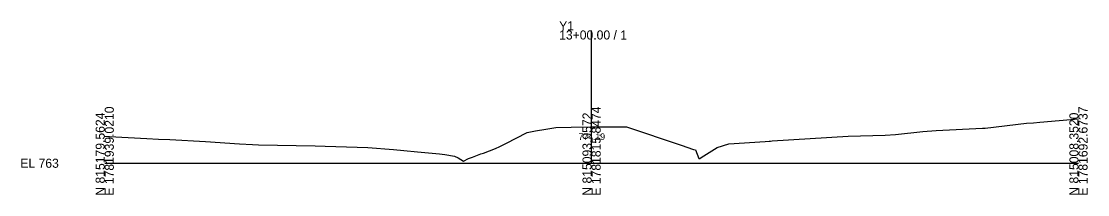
# Model space of a CAD drawing. Extents: x -26 to 3603, y -10 to 9847.
# Drawn here: x -25.7 to 302.8, y 2990.3 to 3043.7 of the extents above; entities that cross this region are included whole.
import ezdxf

# ---------------------------------------------------------------- set-up
doc = ezdxf.new("R2010")
doc.units = 0
for name, color, linetype in [('Exist Cross Section Cell', 7, 'Continuous'), ('Exist XS Center Line Elevation Label', 7, 'Continuous'), ('Exist XS Ground Line', 7, 'Continuous')]:
    doc.layers.add(name, color=color, linetype=linetype)

msp = doc.modelspace()

# ---------------------------------------------------------------- linework, layer by layer
at = {"layer": 'Exist Cross Section Cell'}
for p, q in [((150, 3000), (150, 3040.93)), ((0, 3000), (150, 3000)), ((150, 3000), (300, 3000))]:
    msp.add_line(p, q, dxfattribs=at)
at = {"layer": 'Exist XS Ground Line'}
for p, q in [((286.14, 3012.49), (288.1, 3012.65)), ((288.1, 3012.65), (300, 3013.64)), ((123.54, 3006.08), (130.13, 3009.51)), ((130.13, 3009.51), (132.75, 3009.96)), ((132.75, 3009.96), (135.87, 3010.5)), ((135.87, 3010.5), (139.03, 3011.03)), ((139.03, 3011.03), (143.7, 3011.11)), ((143.7, 3011.11), (149.68, 3011.19)), ((149.68, 3011.19), (150, 3011.19)), ((150, 3011.19), (156.1, 3011.21)), ((156.1, 3011.21), (160.76, 3011.2)), ((160.76, 3011.2), (177.59, 3005.58)), ((243.64, 3008.89), (252.03, 3009.81)), ((252.03, 3009.81), (256.15, 3010.09)), ((256.15, 3010.09), (270.47, 3010.78)), ((270.47, 3010.78), (271.24, 3010.84)), ((271.24, 3010.84), (284.01, 3012.33)), ((284.01, 3012.33), (286.14, 3012.49)), ((0, 3008.32), (1.43, 3008.23)), ((1.43, 3008.23), (13, 3007.61)), ((13, 3007.61), (16.61, 3007.46)), ((16.61, 3007.46), (20.05, 3007.3)), ((20.05, 3007.3), (31, 3006.65)), ((31, 3006.65), (41.51, 3006.02)), ((121.68, 3005.15), (123.54, 3006.08)), ((192.24, 3005.94), (203.44, 3006.71)), ((203.44, 3006.71), (204.72, 3006.81)), ((204.72, 3006.81), (205.13, 3006.82)), ((205.13, 3006.82), (205.66, 3006.86)), ((205.66, 3006.86), (229.08, 3008.35)), ((229.08, 3008.35), (240.42, 3008.65)), ((240.42, 3008.65), (243.64, 3008.89)), ((41.51, 3006.02), (45.51, 3005.79)), ((45.51, 3005.79), (47.36, 3005.71)), ((47.36, 3005.71), (64.81, 3005.31)), ((64.81, 3005.31), (67.88, 3005.21)), ((67.88, 3005.21), (77.8, 3004.99)), ((77.8, 3004.99), (81.03, 3004.81)), ((81.03, 3004.81), (88.95, 3004.19)), ((88.95, 3004.19), (92.14, 3003.91)), ((92.14, 3003.91), (96.4, 3003.53)), ((96.4, 3003.53), (103.19, 3002.87)), ((103.19, 3002.87), (104.81, 3002.68)), ((113.36, 3001.88), (115.88, 3002.94)), ((115.88, 3002.94), (116.73, 3003.15)), ((116.73, 3003.15), (120.35, 3004.54)), ((120.35, 3004.54), (121.68, 3005.15)), ((177.59, 3005.58), (181.41, 3004.21)), ((181.41, 3004.21), (181.98, 3004.11)), ((181.98, 3004.11), (183.04, 3001.41)), ((183.79, 3001.74), (188.7, 3004.81)), ((188.7, 3004.81), (192.24, 3005.94)), ((104.81, 3002.68), (107.74, 3002.21)), ((107.74, 3002.21), (108.86, 3001.62)), ((108.86, 3001.62), (110.55, 3000.67)), ((110.55, 3000.67), (112.08, 3001.46)), ((112.08, 3001.46), (113.36, 3001.88)), ((183.04, 3001.41), (183.36, 3001.44)), ((183.36, 3001.44), (183.79, 3001.74))]:
    msp.add_line(p, q, dxfattribs=at)

# ---------------------------------------------------------------- texts
at = {"layer": 'Exist Cross Section Cell'}
for s, p in [('Y1', (140, 3040.93)), ('13+00.00 / 1', (140, 3038.13)), ('EL 763', (-26, 2998.6))]:
    msp.add_text(s, height=2.8, dxfattribs=at).set_placement(p)
for s, p in [('E 1781939.0210', (2.8, 2990)), ('E 1781815.8474', (152.8, 2990)), ('E 1781692.6737', (302.8, 2990)), ('N 815179.5624', (0, 2990)), ('N 815093.9572', (150, 2990)), ('N 815008.3520', (300, 2990))]:
    msp.add_text(s, height=2.8, rotation=90, dxfattribs=at).set_placement(p)
at = {"layer": 'Exist XS Center Line Elevation Label'}
msp.add_text('774.19', height=2, dxfattribs=at).set_placement((145.97, 3007.19))

doc.saveas('drawing.dxf')
